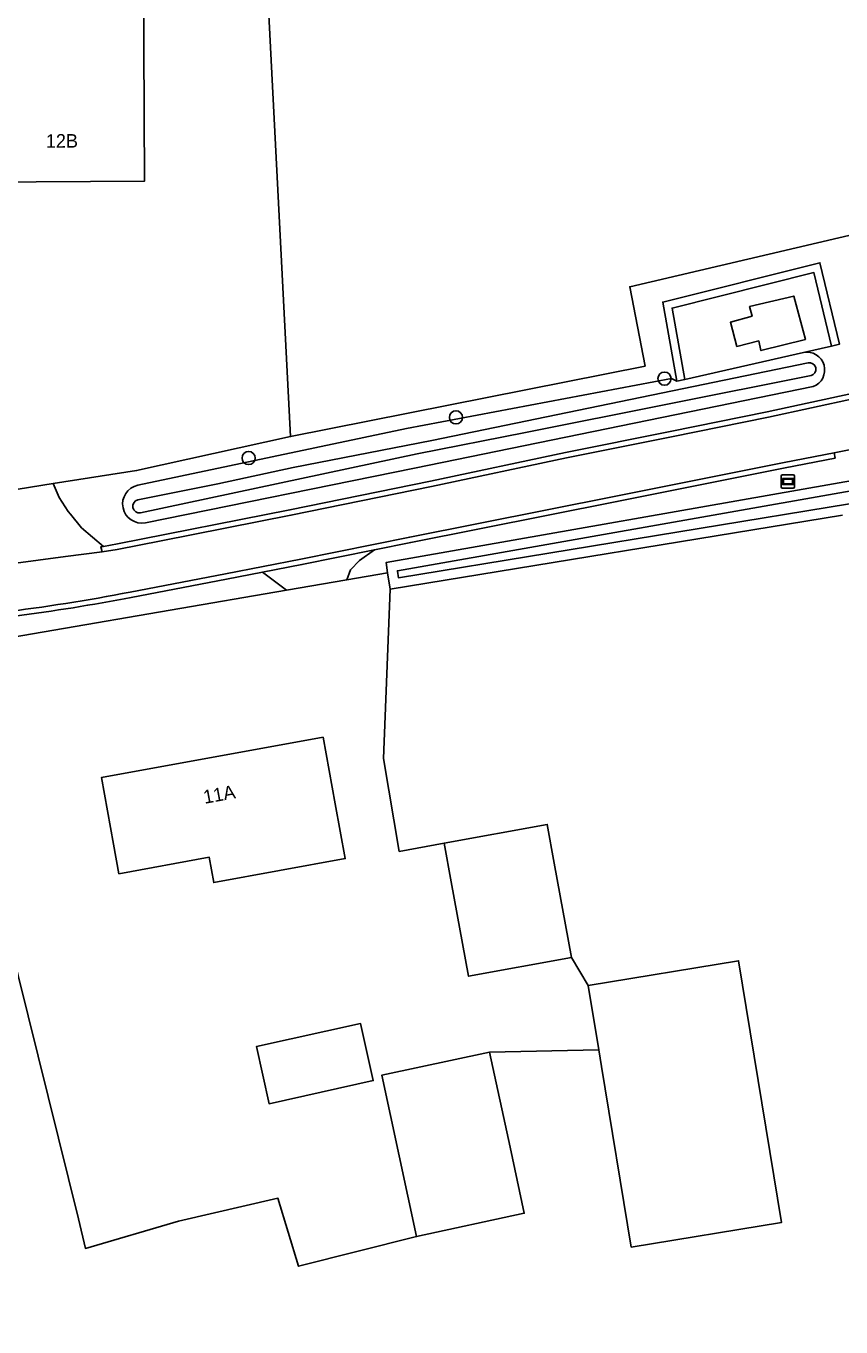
# Model space of a CAD drawing. Extents: x 162510 to 163918, y 388494 to 389774.
# Drawn here: x 163099.2 to 163159.5, y 388914.4 to 389010.7 of the extents above; entities that cross this region are included whole.
import ezdxf

# ---------------------------------------------------------------- set-up
doc = ezdxf.new("R2010")
doc.units = 0
for name, color, linetype in [('IMGEO_Berm_groen', 7, 'Continuous'), ('IMGEO_Boom', 7, 'Continuous'), ('IMGEO_Erf', 7, 'Continuous'), ('IMGEO_Grasland_agrarisch', 7, 'Continuous'), ('IMGEO_Grasland_overig', 7, 'Continuous'), ('IMGEO_Groenvoorziening', 7, 'Continuous'), ('IMGEO_Haag', 7, 'Continuous'), ('IMGEO_Loofbos', 7, 'Continuous'), ('IMGEO_Oever', 7, 'Continuous'), ('IMGEO_Pand', 7, 'Continuous'), ('IMGEO_Pand_nummerreeks', 7, 'Continuous'), ('IMGEO_Rijbaan_lokaal_gesloten', 7, 'Continuous'), ('IMGEO_Rijbaan_lokaal_halfverhard', 7, 'Continuous'), ('IMGEO_Rijbaan_lokaal_open', 7, 'Continuous'), ('IMGEO_Voetpad_halfverhard', 7, 'Continuous'), ('IMGEO_Waterloop', 7, 'Continuous'), ('IMGEO_Wegwijzer', 7, 'Continuous')]:
    doc.layers.add(name, color=color, linetype=linetype)

msp = doc.modelspace()

# ---------------------------------------------------------------- linework, layer by layer
at = {"layer": 'IMGEO_Berm_groen'}
msp.add_lwpolyline([(163161.316, 388979.553), (163158.963, 388979.09), (163159.04, 388978.698), (163155.345, 388977.971), (163142.884, 388975.48), (163127.634, 388972.457), (163124.953, 388971.91), (163123.835, 388971.112), (163123.16, 388970.437), (163122.893, 388969.691), (163125.918, 388970.212), (163125.807, 388970.958), (163161.159, 388977.199)], dxfattribs=at)
at = {"layer": 'IMGEO_Boom'}
for centre in [(163146.409, 388984.587), (163130.979, 388981.715), (163115.632, 388978.707)]:
    msp.add_circle(centre, 0.489, dxfattribs=at)
at = {"layer": 'IMGEO_Erf'}
msp.add_lwpolyline([(163052.563, 389020.587), (163052.851, 389006.121), (163052.866, 389005.347), (163053.09, 388994.093), (163053.454, 388975.765), (163074.891, 388975.272), (163093.207, 388975.56), (163097.673, 388976.261), (163101.17, 388976.81), (163107.335, 388977.778), (163118.731, 388980.29), (163115.27, 389047.574)], dxfattribs=at)
for points in [[(163095.881, 388999.142), (163095.686, 389039.216), (163107.726, 389039.275), (163107.921, 388999.201)], [(163130.634, 388947.318), (163130.113, 388950.183), (163126.78, 388949.576), (163125.622, 388956.459), (163126.1, 388968.984), (163125.918, 388970.212), (163122.893, 388969.691), (163118.423, 388968.921), (163092.585, 388964.47), (163103.049, 388922.376), (163103.547, 388920.178), (163110.429, 388922.204), (163117.794, 388923.892), (163119.326, 388918.852), (163128.061, 388921.054), (163125.484, 388932.995), (163133.459, 388934.716), (163141.553, 388934.877), (163140.769, 388939.653), (163139.523, 388941.721), (163131.905, 388940.334)], [(163106.036, 388947.922), (163105.636, 388950.119), (163104.74, 388955.038), (163121.142, 388958.024), (163122.038, 388953.105), (163122.778, 388949.04), (163113.055, 388947.27), (163112.715, 388949.138)], [(163123.921, 388936.828), (163124.859, 388932.604), (163117.148, 388930.891), (163116.209, 388935.116)]]:
    msp.add_lwpolyline(points, close=True, dxfattribs=at)
at = {"layer": 'IMGEO_Grasland_agrarisch'}
for points in [[(163115.27, 389047.574), (163118.731, 388980.29), (163144.973, 388985.514), (163143.845, 388991.391), (163162.895, 388995.848)], [(163159.581, 388974.479), (163126.1, 388968.984), (163125.622, 388956.459), (163126.78, 388949.576), (163130.113, 388950.183), (163137.729, 388951.57), (163138.251, 388948.705), (163139.523, 388941.721), (163140.769, 388939.653), (163151.895, 388941.479), (163155.075, 388922.105), (163143.949, 388920.279), (163141.755, 388933.644), (163141.553, 388934.877), (163133.459, 388934.716), (163134.979, 388927.671), (163136.036, 388922.775), (163128.061, 388921.054), (163119.326, 388918.852), (163117.794, 388923.892), (163110.429, 388922.204), (163103.547, 388920.178), (163103.049, 388922.376), (163092.585, 388964.47)]]:
    msp.add_lwpolyline(points, dxfattribs=at)
at = {"layer": 'IMGEO_Grasland_overig'}
for points in [[(163157.47, 388992.44), (163146.969, 388989.812), (163147.904, 388984.523), (163156.692, 388986.523), (163158.778, 388986.998)], [(163151.286, 388988.763), (163152.893, 388989.207), (163152.708, 388989.927), (163155.982, 388990.701), (163156.837, 388987.485), (163153.545, 388986.668), (163153.39, 388987.375), (163151.766, 388986.968)]]:
    msp.add_lwpolyline(points, close=True, dxfattribs=at)
for points in [[(163118.423, 388968.921), (163116.66, 388970.246), (163113.993, 388969.727), (163106.949, 388968.38)], [(163089.586, 388966.085), (163090.188, 388964.057), (163092.585, 388964.47), (163118.423, 388968.921)]]:
    msp.add_lwpolyline(points, dxfattribs=at)
msp.add_arc((163077.903, 389121.3), 155.654, 274.30444, 280.7547, dxfattribs=at)
at = {"layer": 'IMGEO_Groenvoorziening'}
msp.add_lwpolyline([(163147.904, 388984.523), (163146.969, 388989.812), (163157.47, 388992.44), (163158.778, 388986.998), (163159.363, 388987.131), (163157.912, 388993.169), (163146.281, 388990.258), (163147.318, 388984.39)], close=True, dxfattribs=at)
at = {"layer": 'IMGEO_Haag'}
msp.add_lwpolyline([(163147.904, 388984.523), (163146.969, 388989.812), (163157.47, 388992.44), (163158.778, 388986.998), (163159.363, 388987.131), (163157.912, 388993.169), (163146.281, 388990.258), (163147.318, 388984.39)], close=True, dxfattribs=at)
at = {"layer": 'IMGEO_Loofbos'}
for points in [[(163162.895, 388995.848), (163143.845, 388991.391), (163144.973, 388985.514), (163118.731, 388980.29), (163107.335, 388977.778), (163101.17, 388976.81), (163101.606, 388975.776), (163102.282, 388974.746), (163102.437, 388974.556), (163103.264, 388973.544), (163104.899, 388972.165), (163105.937, 388972.354), (163118.681, 388974.863), (163129.084, 388976.995), (163139.083, 388979.104), (163146.842, 388980.67), (163154.022, 388982.13), (163163.572, 388984.19)], [(163107.419, 388976.69), (163127.322, 388980.898), (163146.929, 388984.6), (163147.318, 388984.39), (163146.281, 388990.258), (163157.912, 388993.169), (163159.363, 388987.131)], [(163159.363, 388987.131), (163158.778, 388986.998), (163156.692, 388986.523)], [(163157.411, 388983.99), (163127.899, 388977.962), (163107.992, 388973.912)]]:
    msp.add_lwpolyline(points, dxfattribs=at)
for centre, radius, start, end in [((163156.947, 388985.227), 1.321, 290.54802, 101.1455), ((163107.724, 388975.305), 1.418, 102.41781, 280.89135)]:
    msp.add_arc(centre, radius, start, end, dxfattribs=at)
at = {"layer": 'IMGEO_Oever'}
for points in [[(163156.692, 388986.523), (163147.904, 388984.523), (163147.318, 388984.39), (163146.929, 388984.6), (163127.322, 388980.898), (163107.419, 388976.69)], [(163129.203, 388980.013), (163157.042, 388985.752)], [(163157.255, 388984.805), (163136.118, 388980.601), (163128.11, 388979.02), (163107.633, 388974.644)], [(163107.992, 388973.912), (163127.899, 388977.962), (163157.411, 388983.99)], [(163107.437, 388975.611), (163113.361, 388976.795), (163118.936, 388978.006), (163129.203, 388980.013)], [(163182.1, 388914.357), (163181.123, 388917.659), (163179.642, 388921.834), (163177.299, 388927.553), (163169.621, 388950.367), (163161.379, 388976.501), (163161.159, 388977.199), (163125.807, 388970.958), (163125.918, 388970.212), (163126.1, 388968.984), (163159.581, 388974.479)], [(163181.149, 388914.477), (163181.106, 388914.605), (163180.866, 388915.308), (163178.668, 388921.754), (163177.214, 388925.303), (163167.579, 388950.613), (163160.102, 388975.315), (163126.722, 388969.836), (163126.65, 388970.321), (163126.645, 388970.354), (163160.648, 388976.357), (163160.673, 388976.278), (163168.917, 388950.138), (163176.605, 388927.294), (163178.95, 388921.57), (163180.417, 388917.433), (163180.49, 388917.18)]]:
    msp.add_lwpolyline(points, dxfattribs=at)
for centre, radius, start, end in [((163156.947, 388985.227), 1.321, 290.54802, 101.1455), ((163157.127, 388985.274), 0.486, 285.23068, 100.12145), ((163107.724, 388975.305), 1.418, 102.41781, 280.89135), ((163107.557, 388975.132), 0.494, 104.05169, 278.86427)]:
    msp.add_arc(centre, radius, start, end, dxfattribs=at)
at = {"layer": 'IMGEO_Pand'}
for points in [[(163095.881, 388999.142), (163107.921, 388999.201), (163107.726, 389039.275), (163095.686, 389039.216)], [(163153.545, 388986.668), (163156.837, 388987.485), (163155.982, 388990.701), (163152.708, 388989.927), (163152.893, 388989.207), (163151.286, 388988.763), (163151.766, 388986.968), (163153.39, 388987.375)], [(163122.038, 388953.105), (163121.142, 388958.024), (163104.74, 388955.038), (163105.636, 388950.119), (163106.036, 388947.922), (163112.715, 388949.138), (163113.055, 388947.27), (163122.778, 388949.04)], [(163138.251, 388948.705), (163137.729, 388951.57), (163130.113, 388950.183), (163130.634, 388947.318), (163131.905, 388940.334), (163139.523, 388941.721)], [(163151.895, 388941.479), (163140.769, 388939.653), (163141.553, 388934.877), (163141.755, 388933.644), (163143.949, 388920.279), (163155.075, 388922.105)], [(163117.148, 388930.891), (163124.859, 388932.604), (163123.921, 388936.828), (163116.209, 388935.116)], [(163133.459, 388934.716), (163125.484, 388932.995), (163128.061, 388921.054), (163136.036, 388922.775), (163134.979, 388927.671)]]:
    msp.add_lwpolyline(points, close=True, dxfattribs=at)
at = {"layer": 'IMGEO_Rijbaan_lokaal_gesloten'}
for points in [[(163172.94, 388985.959), (163163.656, 388983.799), (163154.102, 388981.738), (163146.921, 388980.278), (163139.166, 388978.713), (163129.164, 388976.603), (163118.761, 388974.471), (163109.164, 388972.585), (163105.911, 388971.943), (163104.779, 388971.756), (163102.066, 388971.421), (163095.614, 388970.542), (163092.059, 388970.078)], [(163106.874, 388968.773), (163113.917, 388970.12), (163119.491, 388971.205), (163127.556, 388972.849), (163142.806, 388975.872), (163155.267, 388978.363), (163158.963, 388979.09), (163161.316, 388979.553)]]:
    msp.add_lwpolyline(points, dxfattribs=at)
msp.add_arc((163077.92, 389121.179), 155.132, 273.61082, 280.75683, dxfattribs=at)
at = {"layer": 'IMGEO_Rijbaan_lokaal_halfverhard'}
for points in [[(163172.849, 388986.349), (163163.572, 388984.19), (163154.022, 388982.13), (163146.842, 388980.67), (163139.083, 388979.104), (163129.084, 388976.995), (163118.681, 388974.863), (163105.937, 388972.354), (163104.899, 388972.165), (163104.69, 388972.127), (163104.779, 388971.756), (163105.911, 388971.943), (163109.164, 388972.585), (163118.761, 388974.471), (163129.164, 388976.603), (163139.166, 388978.713), (163146.921, 388980.278), (163154.102, 388981.738), (163163.656, 388983.799), (163172.94, 388985.959)], [(163158.963, 388979.09), (163155.267, 388978.363), (163142.806, 388975.872), (163127.556, 388972.849), (163119.491, 388971.205), (163113.917, 388970.12), (163106.874, 388968.773)], [(163106.949, 388968.38), (163113.993, 388969.727), (163116.66, 388970.246), (163119.571, 388970.813), (163124.953, 388971.91), (163127.634, 388972.457), (163142.884, 388975.48), (163155.345, 388977.971), (163159.04, 388978.698), (163158.963, 388979.09)]]:
    msp.add_lwpolyline(points, dxfattribs=at)
for centre, radius, start, end in [((163077.92, 389121.179), 155.132, 273.61082, 280.75683), ((163077.903, 389121.3), 155.654, 274.30444, 280.7547)]:
    msp.add_arc(centre, radius, start, end, dxfattribs=at)
at = {"layer": 'IMGEO_Rijbaan_lokaal_open'}
msp.add_lwpolyline([(163103.264, 388973.544), (163102.437, 388974.556), (163102.282, 388974.746), (163101.606, 388975.776), (163101.17, 388976.81), (163097.673, 388976.261), (163097.756, 388975.067), (163097.56, 388973.869), (163097.514, 388973.745), (163097.048, 388972.504), (163095.679, 388970.691), (163095.607, 388970.596), (163095.614, 388970.542), (163102.066, 388971.421), (163104.779, 388971.756), (163104.69, 388972.127), (163104.899, 388972.165)], close=True, dxfattribs=at)
at = {"layer": 'IMGEO_Voetpad_halfverhard'}
msp.add_lwpolyline([(163123.16, 388970.437), (163123.835, 388971.112), (163124.953, 388971.91), (163119.571, 388970.813), (163116.66, 388970.246), (163118.423, 388968.921), (163122.893, 388969.691)], close=True, dxfattribs=at)
at = {"layer": 'IMGEO_Waterloop'}
for points in [[(163157.042, 388985.752), (163129.203, 388980.013), (163118.936, 388978.006), (163113.361, 388976.795), (163107.437, 388975.611)], [(163107.633, 388974.644), (163128.11, 388979.02), (163136.118, 388980.601), (163157.255, 388984.805)], [(163181.454, 388914.539), (163181.385, 388914.728), (163180.49, 388917.18), (163180.417, 388917.433), (163178.95, 388921.57), (163176.605, 388927.294), (163168.917, 388950.138), (163160.673, 388976.278), (163160.648, 388976.357), (163126.645, 388970.354), (163126.65, 388970.321), (163126.722, 388969.836), (163160.102, 388975.315), (163167.579, 388950.613), (163177.214, 388925.303), (163178.668, 388921.754), (163180.866, 388915.308)]]:
    msp.add_lwpolyline(points, dxfattribs=at)
for centre, radius, start, end in [((163157.127, 388985.274), 0.486, 285.23068, 100.12145), ((163107.557, 388975.132), 0.494, 104.05169, 278.86427)]:
    msp.add_arc(centre, radius, start, end, dxfattribs=at)
at = {"layer": 'IMGEO_Wegwijzer'}
for p, q in [((163155.053, 388976.567), (163155.053, 388977.367)), ((163155.053, 388977.367), (163155.053, 388976.567)), ((163155.153, 388977.467), (163155.943, 388977.467)), ((163155.943, 388977.467), (163155.153, 388977.467)), ((163156.043, 388977.367), (163156.043, 388976.567)), ((163156.043, 388976.567), (163156.043, 388977.367)), ((163155.943, 388976.467), (163155.153, 388976.467)), ((163155.153, 388976.467), (163155.943, 388976.467))]:
    msp.add_line(p, q, dxfattribs=at)
for points in [[(163155.154, 388977.199), (163155.942, 388977.199), (163155.942, 388976.735), (163155.154, 388976.735), (163155.154, 388977.199)], [(163155.219, 388977.134), (163155.219, 388976.8), (163155.877, 388976.8), (163155.877, 388977.134), (163155.219, 388977.134)]]:
    msp.add_lwpolyline(points, dxfattribs=at)
for centre, start, end in [((163155.153, 388977.367), 90, 180), ((163155.153, 388977.367), 90, 180), ((163155.153, 388976.567), 180, 270), ((163155.153, 388976.567), 180, 270), ((163155.943, 388977.367), 0, 90), ((163155.943, 388977.367), 360, 90), ((163155.943, 388976.567), 270, 0), ((163155.943, 388976.567), 270, 0)]:
    msp.add_arc(centre, 0.1, start, end, dxfattribs=at)

# ---------------------------------------------------------------- texts
at = {"layer": 'IMGEO_Pand_nummerreeks'}
for s, rotation, p in [('12B', 0.28077, (163100.624, 389001.685)), ('11A', 10.31776, (163112.374, 388953.094))]:
    msp.add_text(s, height=1, rotation=rotation, dxfattribs=at).set_placement(p)

doc.saveas('drawing.dxf')
